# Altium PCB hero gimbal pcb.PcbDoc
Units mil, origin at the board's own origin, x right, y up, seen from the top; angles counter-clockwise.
Board outline 2559.06 x 1968.5 mil, 2 copper layers (Top Layer, Bottom Layer); 13 components, 14 nets, 60 pads, 0 vias.
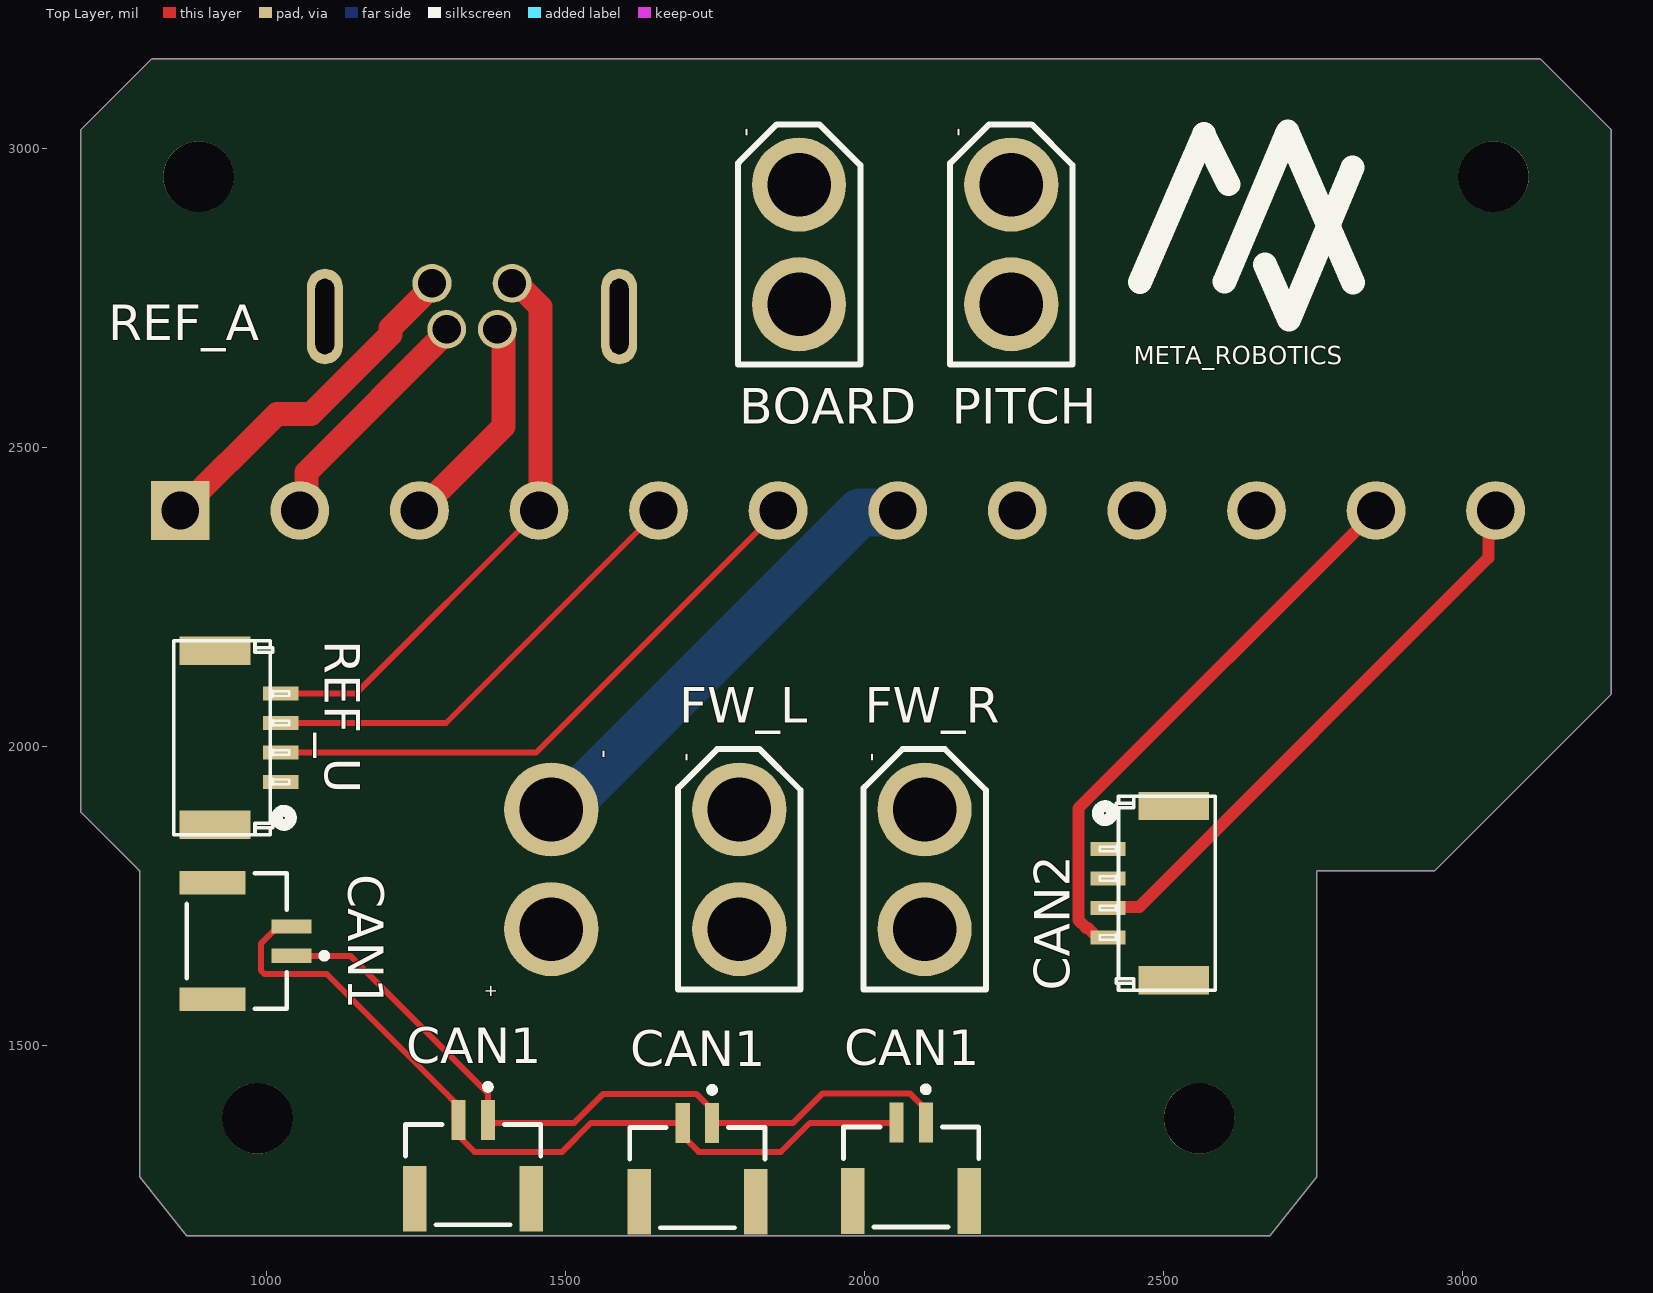
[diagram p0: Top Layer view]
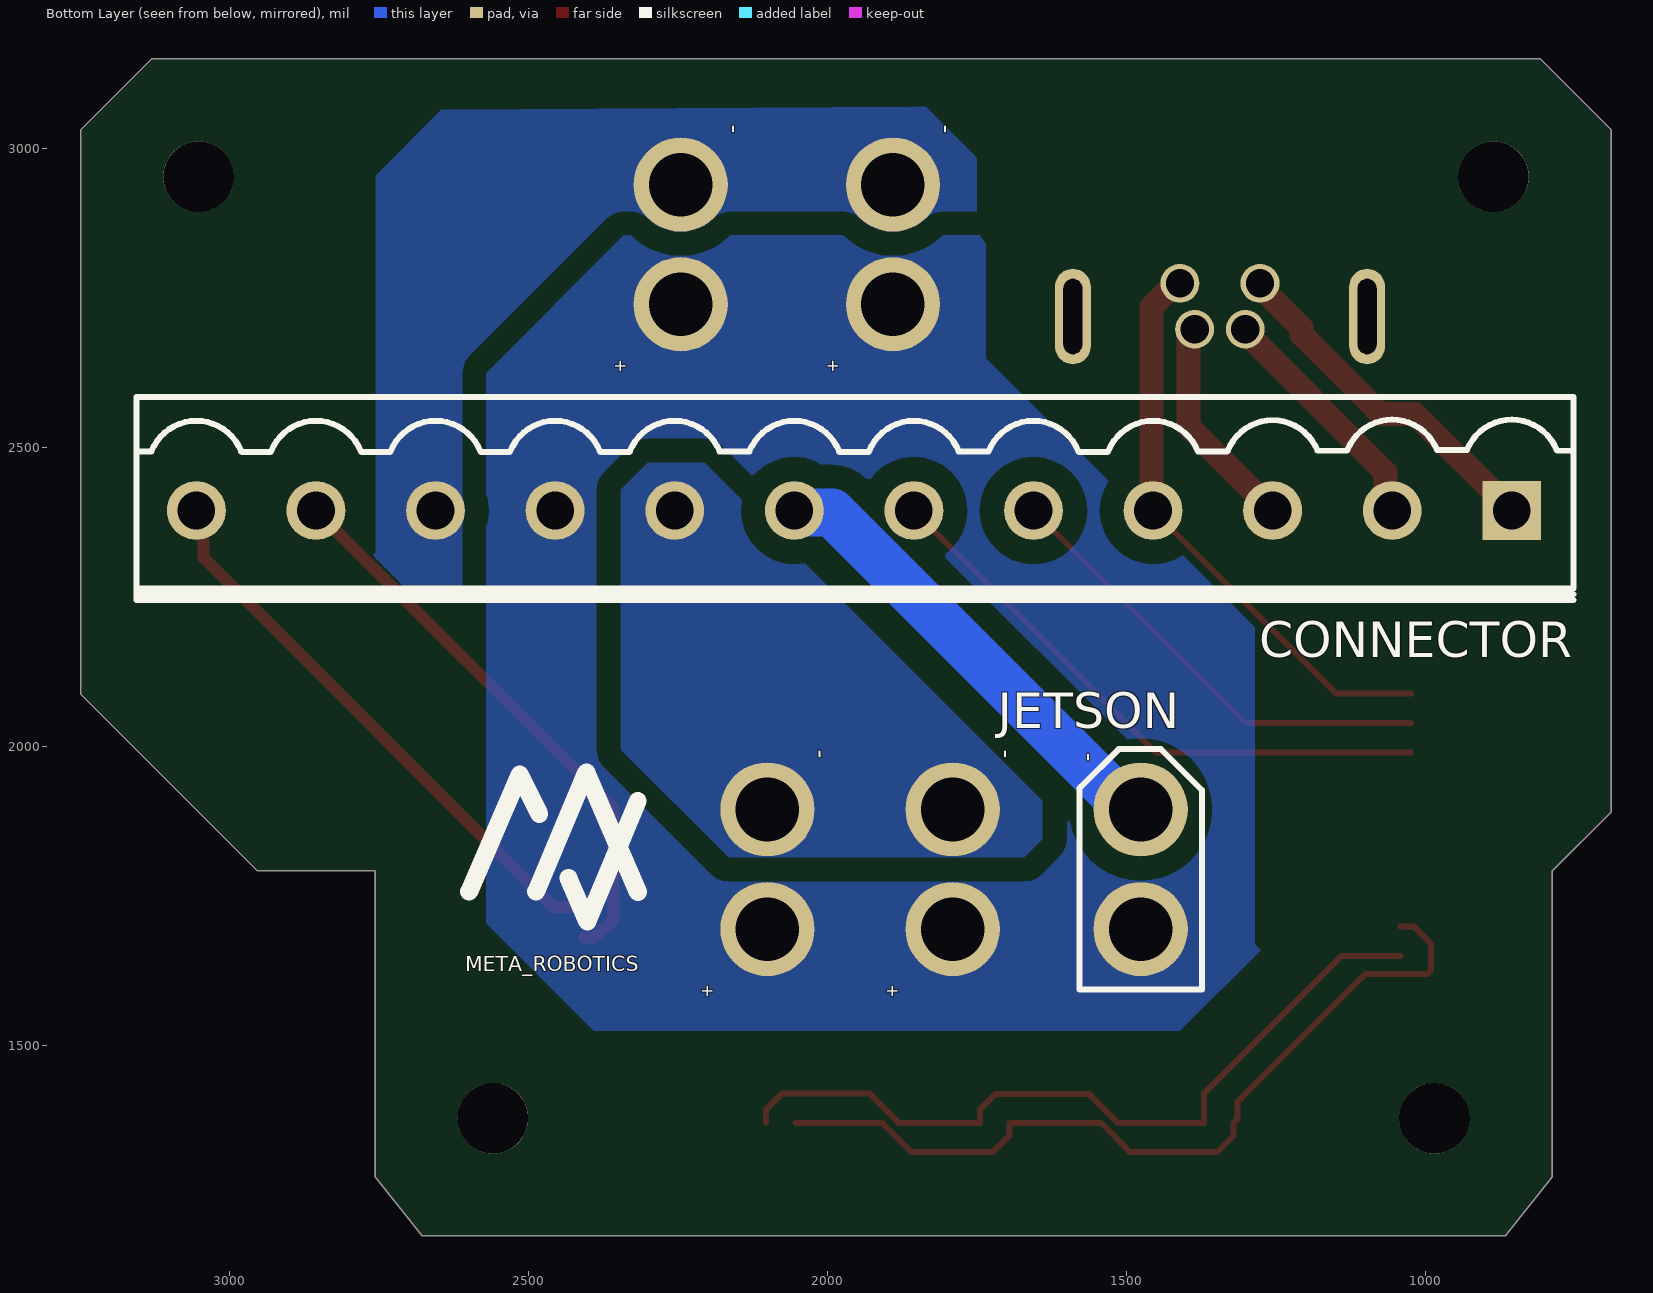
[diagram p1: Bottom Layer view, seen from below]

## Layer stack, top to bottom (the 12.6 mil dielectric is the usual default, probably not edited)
Top Solder: solder mask 0.4, Solder Resist, Dk 3.5
Top Layer: signal copper 1.4
Dielectric 1: dielectric 12.6, FR-4, Dk 4.8
Bottom Layer: signal copper 1.4
Bottom Solder: solder mask 0.4, Solder Resist, Dk 3.5

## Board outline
866.14,1181.79 787.4,1280.71 787.4,1792.19 688.98,1890.61 688.98,3032.19 807.09,3150.3 3129.92,3150.3 3248.03,3032.19 3248.03,2087.46 2952.76,1792.19 2755.91,1792.19 2755.91,1280.71 2677.17,1181.79

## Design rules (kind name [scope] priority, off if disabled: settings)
Clearance Clearance_p [InPolygon] p1: gap=40 ignorepadtopadclearanceinfootprint=FALSE
PlaneClearance [All] p1: clearance=80
PolygonConnect [All] p1: connectstyle=Direct reliefconductorwidth=10 reliefentries=4 polygonreliefangle="90 Angle" airgapwidth=10
RoutingVias [All] p1: holewidth=28 width=50 viastyle="Through Hole" minholewidth=28 minwidth=50 maxholewidth=28 maxwidth=50
SolderMaskExpansion [All] p1: expansion=4 istentingtop=FALSE
Width [All] p1: maxlimit=80 minlimit=10 preferedwidth=20
29 further rules are at their usual default settings.

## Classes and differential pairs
component class Schematic: BOARD CAN1 CAN2 CONNECTOR FW_L FW_R JETSON PITCH REF_A REF_U

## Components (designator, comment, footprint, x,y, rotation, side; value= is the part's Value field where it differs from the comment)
BOARD "XT PLUGIN" XT30-M 1890,2840 r90 top
CAN1 "CAN1" JST-BM02B-GHS-TBT_V 2077.44,1305.94 r180 top
CAN1 "CAN1" JST-BM02B-GHS-TBT_V 1720,1305 r180 top
CAN1 "CAN1" JST-BM02B-GHS-TBT_V 975,1675 r90 top
CAN1 "CAN1" JST-BM02B-GHS-TBT_V 1345,1310 r180 top
CAN2 "gh1.25_4p" GH1.25-LS-4P 2505,1755 r90 top
CONNECTOR "HDR-1X12" KF2EDGK5.08-LI-12P 1955,2395 r0 bottom
FW_L "XT PLUGIN" XT30-M 1790,1795 r90 top
FW_R "XT PLUGIN" XT30-M 2100,1795 r90 top
JETSON "XT PLUGIN" XT30-M 1475.67,1795 r90 bottom
PITCH "XT PLUGIN" XT30-M 2245,2840 r90 top
REF_A "Referee_Air" "M8 Connector" 1343.07,2737.6 r180 top
REF_U "gh1.25_4p" GH1.25-LS-4P 925,2015 r270 top

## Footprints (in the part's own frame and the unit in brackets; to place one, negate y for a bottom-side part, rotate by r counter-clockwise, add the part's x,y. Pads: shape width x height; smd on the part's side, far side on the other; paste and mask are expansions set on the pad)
GH1.25-LS-4P [mm] "A1257WR-S-4P"
  rect 1.2x3 smd: 0(-3.7,-0.3) 0(3.7,-0.3)
  rect 0.6x1.5 smd: 1(1.875,2.5) 2(0.625,2.5) 3(-0.625,2.5) 4(-1.875,2.5)
  silkscreen extent -4.13,-2.05 4.12,2.93, body extent -4.12,-2.15 4.12,2.25, height 4.2
JST-BM02B-GHS-TBT_V [mm] "Connector, 2-Leads, Body 5.75x4.25mm, Pitch 1.25mm"
  rect 0.6x1.7 smd: 1(-0.625,-1.675) 2(0.625,-1.675)
  rect 1x2.8 smd: MP1(-2.475,1.675) MP2(2.475,1.675)
  silkscreen extent -2.88,-3.2 2.88,2.78, body extent -2.88,-2.17 2.87,2.78, height 4.21
KF2EDGK5.08-LI-12P [mm] "立插端子"
  rect 2.5x2.5 hole 1.6: 1(-27.94,0)
  round 2.5 hole 1.6: 2(-22.86,0) 3(-17.78,0) 4(-12.7,0) 5(-7.62,0) 6(-2.54,0) 7(2.54,0) 8(7.62,0) 9(12.7,0) 10(17.78,0) 11(22.86,0) 12(27.94,0)
  silkscreen extent -30.56,-4.83 30.48,3.81, body extent -30.48,-4.75 30.48,3.75, height 11.25
"M8 Connector" [mm]
  round 1.65 hole 1.2: 0(-1.075,1) 1(1.075,1) 2(-1.7,-0.95) 3(1.7,-0.95)
  oval 1.524x4.064 hole 0.8 slot 3.2 at 90 deg: 4(-6.25,0.46) 5(6.25,0.46)
  body extent -6.25,-19.34 6.25,1.96, height 11.3
XT30-M [mm]
  round 4 hole 2.7: 1(-2.54,0) 2(2.54,0)
  silkscreen extent -5.1,-2.6 5.11,2.6, body extent -5.18,-2.8 5.02,2.8, height 10.66

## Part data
CAN1 CAN1 CAN1 CAN1: library part CMP-2000-05957-1, "Disconnectable Crimp Style Connector, Pitch 1.25 mm, 1 x 2 Position, Height 4.05 mm, -25 to 85 degC, RoHS, Tape and Reel", Color=Natural, Manufacturer=JST-Sales-America-Inc., Package Description="Disconnectable Crimp Style Connector, Pitch 1.25 mm, 1 x 2 Position, Height 4.05 mm", Package Reference=BM02B-GHS-TBT
CONNECTOR: library part "Header 12", "12P接插件"

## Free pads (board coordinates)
  round 118.11 hole 118.11: ""(885.83,2953.45) ""(984.25,1378.64) ""(2559.06,1378.64) ""(3051.18,2953.45)

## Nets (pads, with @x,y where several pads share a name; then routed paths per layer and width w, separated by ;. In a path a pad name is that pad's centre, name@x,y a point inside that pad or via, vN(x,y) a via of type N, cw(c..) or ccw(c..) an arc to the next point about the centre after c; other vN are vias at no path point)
AMMO_DC: CONNECTOR.8 FW_L.2 FW_R.2
CAN1_H: CAN1.2 | length 1398.8
  Top Layer w10: CAN1.2@1040.94,1699.61 1019.29,1699.61 990,1670.32 990,1625.86 995.86,1620 1100,1620 1300,1420 1313.58,1406.41 1313.58,1377.76 1320.39,1370.94 1320.39,1349.29 1347.2,1322.48 1493.66,1322.48 1542.13,1370.94 1695.39,1370.94 1695.39,1349.29 1722.2,1322.48 1859.88,1322.48 1908.35,1370.94 2051.89,1370.94 CAN1.2@2052.83,1371.89
CAN1_L: CAN1.1 | length 1311.9
  Top Layer w10: CAN1.1@1040.94,1650.39 1139.61,1650.39 1369.61,1420.39 1369.61,1370.94 1513.84,1370.94 1562.31,1419.41 1717.8,1419.41 1744.61,1392.6 1744.61,1370.94 1880.06,1370.94 1929.47,1420.35 2075.24,1420.35 2102.05,1393.54 CAN1.1@2102.05,1371.89
CAN2_H: CAN2.3 CONNECTOR.12 | length 963
  Top Layer w20: CAN2.3 2408.39,1732.2 2459.31,1732.2 3042.89,2315.79 3042.89,2382.9 CONNECTOR.12
CAN2_L: CAN2.4 CONNECTOR.11 | length 952.5
  Top Layer w20: CAN2.4 2388.86,1681.18 2372.91,1697.13 2370.21,1697.13 2357.05,1710.3 2357.05,1897.05 CONNECTOR.11
GIMBAL_DC: BOARD.2 CONNECTOR.10 PITCH.2
GND: BOARD.1 CONNECTOR.9 FW_L.1 FW_R.1 JETSON.1 PITCH.1
MPC_DC: CONNECTOR.7 JETSON.2 | length 786.4
  Bottom Layer w80: JETSON.2 1495.31,1895 1991.78,2391.47 2051.47,2391.47 CONNECTOR.7
REFEREE_A1: CONNECTOR.3 REF_A.0 | length 366.4
  Top Layer w40: CONNECTOR.3 1395.39,2535.39 REF_A.0@1395.39,2703.23
REFEREE_A2: CONNECTOR.2 REF_A.1 | length 414.2
  Top Layer w40: CONNECTOR.2 1066.18,2406.18 1066.18,2458.66 REF_A.1@1310.75,2703.23
REFEREE_A3: CONNECTOR.1 REF_A.3 | length 597.2
  Top Layer w40: CONNECTOR.1 1016.72,2556.73 1074.1,2556.73 1206.61,2689.24 1206.61,2700.47 REF_A.3@1286.14,2780
REFEREE_GND: CONNECTOR.4 REF_A.2 REF_U.4 | length 960.3
  Top Layer w10: REF_U.4 1148.82,2088.82 CONNECTOR.4
  Top Layer w40: REF_A.2@1420,2780 1420,2773.25 1457.87,2735.37 1457.87,2397.87 CONNECTOR.4
REFEREE_UR: CONNECTOR.5 REF_U.3 | length 778.8
  Top Layer w10: REF_U.3 1299.61,2039.61 CONNECTOR.5
REFEREE_UT: CONNECTOR.6 REF_U.2 | length 999.2
  Top Layer w10: REF_U.2 1450.39,1990.39 CONNECTOR.6
pads on no net: CAN1.MP1 CAN1.MP2 CAN2.0 CAN2.1 CAN2.2 REF_A.4 REF_A.5 REF_U.0 REF_U.1

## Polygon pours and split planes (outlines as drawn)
AMMO_DC on Bottom Layer "AMMO_DC_L02_P002" (solid, pour order 2): 1640,1910 2205,2475 2300,2475 2345,2430 2345,1995 2165,1815 1670,1815 1640,1845
GND on Bottom Layer "GND_L02_P006" (solid, pour order 6): 1745,2855 2340,2855 2570,2625 2570,1705 2390,1525 1410,1525 1275,1660 1285,1670 1285,2200 1735,2650 1735,2840
GIMBAL_DC on Bottom Layer "GIMBAL_DC_L02_P009" (solid, pour order 9): 1860,3070 1835,3070 1750,2985 1750,2820 2050,2820 2600,2270 2710,2270 2760,2320 2755,2325 2755,2955 2645,3065
GIMBAL_DC on Bottom Layer "GIMBAL_DC_L02_P008" (solid, pour order 8): 2405,2440

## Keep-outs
Keep-Out Layer:
  the board outline again, w0.5

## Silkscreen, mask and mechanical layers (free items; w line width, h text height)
Top Overlay:
  lines w40: 2460.34,2777.42 2567.15,3024.39 2608.19,2940.63 ; 2601.43,2777.91 2707.28,3028.6 2816.11,2776.31 ; 2669.35,2806.74 2709.6,2714.3 2815.53,2968.43
  text "META_ROBOTICS" at 2450,2640 h30
Bottom Overlay:
  lines w30: 2316.36,1756.7 2402.8,1957.09 2486.88,1757.97 ; 2316.82,1909.3 2400.96,1707.44 2432.93,1780.87 ; 2481.51,1887.22 2514.11,1953.74 2598.95,1757.58
  text "META_ROBOTICS" at 2605,1624.17 h25
Mechanical 1:
  the board outline again, w0.5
